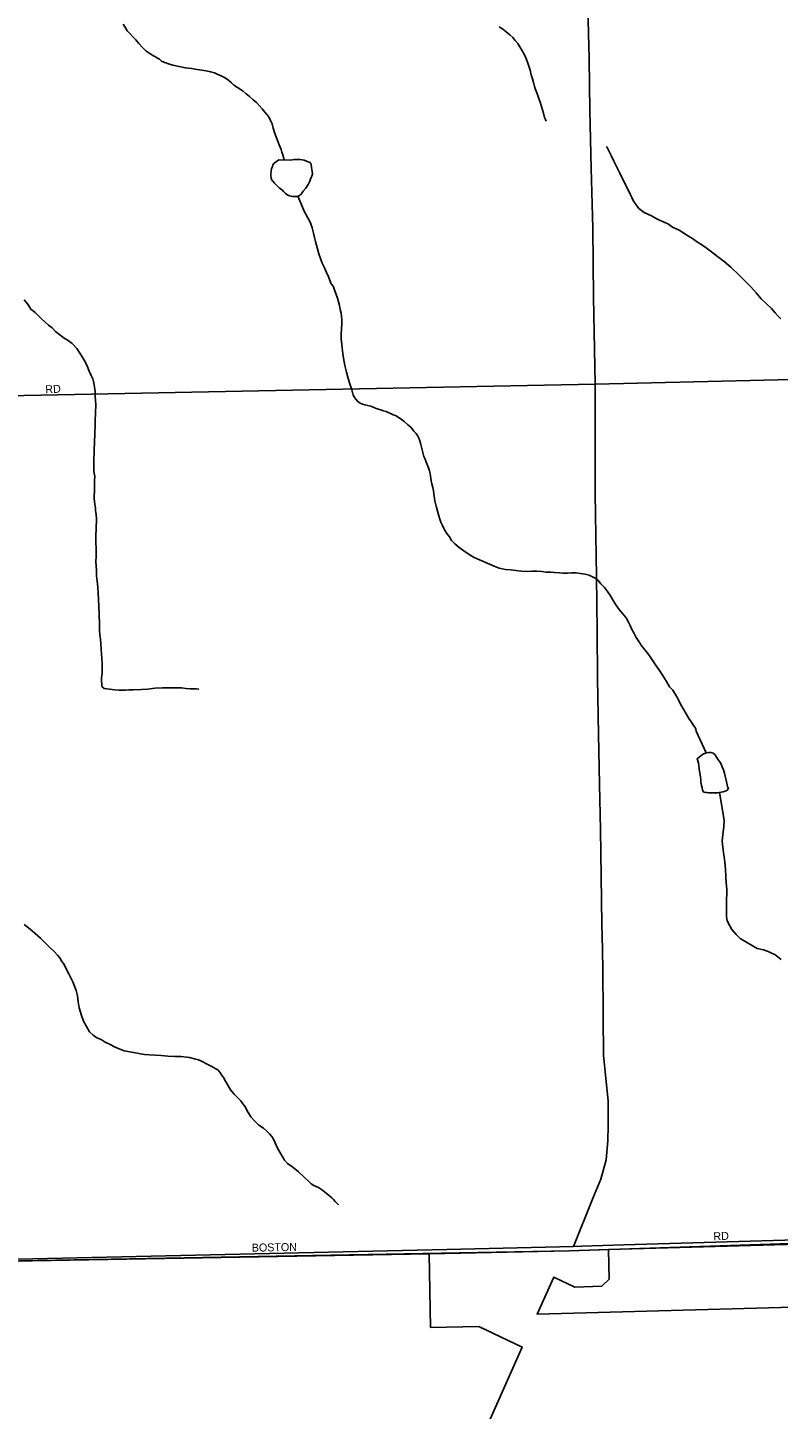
# Model space of a CAD drawing. Extents: x 2010165 to 2382125, y 1060529 to 1407316.
# Drawn here: x 2147720 to 2152412, y 1192922 to 1201555 of the extents above; entities that cross this region are included whole.
import ezdxf

# ---------------------------------------------------------------- set-up
doc = ezdxf.new("R2010")
doc.units = 0
for name, color, linetype in [('GM_X_Adjacent_County', 7, 'Continuous'), ('GM_X_City_Street', 7, 'Continuous'), ('GM_X_City_Street_Text', 7, 'Continuous'), ('GM_X_Corporation', 7, 'Continuous'), ('GM_X_County', 7, 'Continuous'), ('GM_X_Minor_Lake', 7, 'Continuous'), ('GM_X_Minor_River', 7, 'Continuous'), ('GM_X_US_Route', 7, 'Continuous')]:
    doc.layers.add(name, color=color, linetype=linetype)

msp = doc.modelspace()

# ---------------------------------------------------------------- linework, layer by layer
at = {"layer": 'GM_X_Adjacent_County'}
msp.add_lwpolyline([(2158006.9, 1194141.9), (2151106.9, 1193912.6), (2145028.4, 1193800.8), (2144321.2, 1193786.8), (2140581.8, 1193696.4), (2139549.1, 1193676.6), (2134076.1, 1193549.4), (2129443.2, 1193492.7), (2126053.1, 1193488.1), (2117908.3, 1193445.4), (2113522.7, 1193410.7)], dxfattribs=at)
at = {"layer": 'GM_X_City_Street'}
for points in [[(2152235.3, 1199350.5), (2157941.4, 1199486.2)], [(2144971.9, 1199201.6), (2150737.4, 1199316.9)], [(2150737.4, 1199316.9), (2151266.3, 1199327.4)], [(2151266.3, 1199327.4), (2152235.3, 1199350.5)], [(2151447.3, 1193948.6), (2154031.7, 1194024.8)], [(2147752.4, 1193862.6), (2150339.1, 1193921.3)], [(2150339.1, 1193921.3), (2151130.9, 1193939.3), (2151183.6, 1193940.8)], [(2151183.6, 1193940.8), (2151447.3, 1193948.6)], [(2147277.4, 1193851.8), (2147752.4, 1193862.6)]]:
    msp.add_lwpolyline(points, dxfattribs=at)
at = {"layer": 'GM_X_Corporation'}
for points in [[(2154020.1, 1193994.5), (2151351.3, 1193919.5), (2151107.4, 1193912.6), (2150229, 1193893.7), (2145028.4, 1193800.8), (2144321.2, 1193786.8), (2140581.8, 1193696.4), (2139549.1, 1193676.6), (2139563.1, 1207294.1), (2139646.1, 1221239.5)], [(2150282.8, 1192124.7), (2150811.6, 1193309.4), (2150541, 1193440), (2150238.9, 1193433.5), (2150229, 1193893.7), (2151107.4, 1193912.6), (2151351.3, 1193919.5), (2151354.5, 1193736.1), (2151308.4, 1193691.6), (2151140.4, 1193685.8), (2151007.8, 1193747.7), (2150904.4, 1193516.7), (2154025.8, 1193601.1)]]:
    msp.add_lwpolyline(points, dxfattribs=at)
at = {"layer": 'GM_X_County'}
msp.add_lwpolyline([(2158006.9, 1194141.9), (2151106.9, 1193912.6), (2145028.4, 1193800.8), (2144321.2, 1193786.8), (2140581.8, 1193696.4), (2139549.1, 1193676.6), (2139521.7, 1198873.5), (2139522.3, 1201475.3), (2139563.1, 1207294.1), (2139553.6, 1210761.2), (2139571.8, 1213893.1), (2139604.7, 1218402.7), (2139646.1, 1221239.5)], dxfattribs=at)
at = {"layer": 'GM_X_Minor_Lake'}
for points in [[(2149289.2, 1200729.1), (2149275.3, 1200718.8), (2149261.4, 1200708.6), (2149253.5, 1200698.5), (2149249.7, 1200684.4), (2149243.8, 1200674.3), (2149242, 1200658.3), (2149240.2, 1200642.2), (2149240.4, 1200628.1), (2149242.6, 1200616.1), (2149244.7, 1200606.1), (2149252.8, 1200596.2), (2149263, 1200582.3), (2149277.2, 1200568.4), (2149293.5, 1200552.6), (2149311.7, 1200540.7), (2149319.8, 1200530.8), (2149332, 1200518.9), (2149346.1, 1200509.1), (2149356.2, 1200503.2), (2149366.3, 1200501.3), (2149376.3, 1200499.4), (2149392.3, 1200499.6), (2149406.4, 1200499.8), (2149418.3, 1200505.9), (2149430.2, 1200514.1), (2149442, 1200532.3), (2149459.8, 1200552.6), (2149473.5, 1200574.8), (2149483.2, 1200595), (2149491, 1200615.2), (2149496.8, 1200627.3), (2149500.7, 1200639.4), (2149498.5, 1200657.4), (2149496.3, 1200667.4), (2149494.1, 1200683.4), (2149491.9, 1200699.4), (2149485.7, 1200711.4), (2149474.1, 1200717.1)], [(2149474.1, 1200717.1), (2149447.5, 1200727), (2149435.4, 1200728.8), (2149423.4, 1200730.7), (2149407.3, 1200730.5), (2149397.3, 1200730.4), (2149385.3, 1200730.2), (2149375.3, 1200728.1), (2149361.3, 1200727.9), (2149289.2, 1200729.1)], [(2151917.7, 1196923.9), (2151917.4, 1196927), (2151915.1, 1196945), (2151912.9, 1196959.1), (2151908.8, 1196973), (2151904.6, 1196987), (2151937.7, 1197013.2), (2151904.6, 1196987)], [(2151937.7, 1197013.2), (2151950.2, 1197019.7), (2151962.2, 1197023.9), (2151976.2, 1197026), (2151990.2, 1197026.2), (2152004.3, 1197022.4), (2152016.5, 1197010.5), (2152024.6, 1196996.5), (2152036.9, 1196980.6), (2152047.1, 1196966.7), (2152055.3, 1196952.8), (2152061.5, 1196936.8), (2152069.8, 1196916.8), (2152076, 1196896.8), (2152080.3, 1196878.8), (2152084.5, 1196860.8), (2152088.8, 1196842.8), (2152093, 1196824.8), (2152095.2, 1196810.8), (2152101.3, 1196800.8), (2152089.5, 1196788.7), (2152079.5, 1196784.5), (2152067.5, 1196780.4), (2152055.6, 1196778.2), (2152043.6, 1196776.1), (2152031.6, 1196773.9), (2152021.6, 1196773.8), (2152001.5, 1196773.5), (2151991.5, 1196773.4), (2151977.5, 1196773.2), (2151967.4, 1196775.1), (2151957.4, 1196775), (2151945.4, 1196778.9), (2151937.2, 1196790.8), (2151935, 1196806.8), (2151930.8, 1196818.8), (2151928.5, 1196838.9), (2151928.3, 1196854.9), (2151926.1, 1196870.9), (2151917.7, 1196923.9)]]:
    msp.add_lwpolyline(points, dxfattribs=at)
at = {"layer": 'GM_X_Minor_River'}
for points in [[(2148316.4, 1201575.9), (2148330.7, 1201554), (2148341, 1201536), (2148395.8, 1201478.5), (2148414.1, 1201456.7), (2148436.5, 1201432.9), (2148458.8, 1201409.1), (2148483.1, 1201393.3), (2148503.3, 1201381.5), (2148519.4, 1201371.7), (2148531.6, 1201363.8), (2148543.6, 1201357.9), (2148555.8, 1201346.1), (2148572, 1201338.2), (2148606.2, 1201326.6), (2148628.3, 1201320.9), (2148656.4, 1201315.2), (2148706.6, 1201303.8), (2148744.7, 1201300.2), (2148766.9, 1201294.5), (2148795, 1201290.8), (2148835.1, 1201285.3), (2148863.2, 1201279.6), (2148887.4, 1201271.9), (2148905.5, 1201264.1), (2148919.6, 1201258.2), (2148933.7, 1201252.4), (2148945.8, 1201246.5), (2148955.9, 1201238.6), (2148968, 1201232.7), (2148980.2, 1201222.9), (2148994.3, 1201211), (2149008.6, 1201195.1), (2149030.8, 1201181.3), (2149049, 1201169.5), (2149067.2, 1201157.7), (2149085.4, 1201141.9), (2149107.7, 1201124.1), (2149130, 1201104.3), (2149150.2, 1201086.5), (2149168.5, 1201066.7), (2149186.8, 1201046.8), (2149203.1, 1201027), (2149217.3, 1201011.1), (2149229.6, 1200993.2), (2149235.8, 1200979.2), (2149242, 1200967.2), (2149248.2, 1200953.3), (2149254.5, 1200927.3), (2149262.9, 1200899.3), (2149291.9, 1200823.4), (2149298.1, 1200807.4), (2149304.3, 1200793.4), (2149308.6, 1200777.4), (2149312.7, 1200765.5), (2149324.1, 1200728.5)], [(2150666.7, 1201560.6), (2150690.9, 1201544.8), (2150711.1, 1201529), (2150733.5, 1201509.2), (2150751.7, 1201493.4), (2150768, 1201475.5), (2150784.2, 1201455.6), (2150823.2, 1201389.9), (2150833.5, 1201366), (2150843.8, 1201340), (2150852.2, 1201314), (2150860.5, 1201290.1), (2150866.9, 1201260), (2150875.3, 1201236.1), (2150881.6, 1201212.1), (2150887.9, 1201188.1), (2150894.2, 1201168.1), (2150902.5, 1201148.1), (2150908.7, 1201130.1), (2150915, 1201112.1), (2150923.3, 1201090.2), (2150929.5, 1201068.2), (2150937.9, 1201042.2), (2150944.2, 1201020.2), (2150950.6, 1200994.2), (2150956.7, 1200980.2), (2150960.9, 1200970.3)], [(2151339.6, 1200810.4), (2151366.4, 1200756.5), (2151339.6, 1200810.4), (2151366.4, 1200756.5), (2151382.9, 1200720.6), (2151403.4, 1200682.8), (2151421.9, 1200644.9), (2151465.2, 1200557.1), (2151477.5, 1200533.2), (2151487.8, 1200511.2), (2151496, 1200493.3), (2151504.3, 1200475.3), (2151516.6, 1200455.4), (2151528.8, 1200439.5), (2151541, 1200425.6), (2151557.2, 1200411.8), (2151573.4, 1200399.9), (2151595.6, 1200390.2), (2151619.8, 1200378.4), (2151644, 1200364.7), (2151670.2, 1200353), (2151698.4, 1200339.3), (2151724.6, 1200327.6), (2151750.9, 1200307.8), (2151791.2, 1200290.2), (2151821.5, 1200270.6), (2151849.8, 1200252.8), (2151876, 1200237.1), (2151900.3, 1200219.4), (2151928.6, 1200201.6), (2151960.9, 1200180), (2151993.3, 1200154.3), (2152031.8, 1200124.7), (2152074.3, 1200093.1), (2152114.8, 1200057.5), (2152167.5, 1200007.9), (2152204.1, 1199970.3), (2152240.6, 1199934.6), (2152273.2, 1199898.9), (2152305.7, 1199861.2), (2152340.2, 1199827.5), (2152368.6, 1199799.7), (2152393, 1199774), (2152411.3, 1199752.1), (2152427.6, 1199736.3)], [(2149409.2, 1200501.2), (2149449.7, 1200404), (2149484.5, 1200344.2), (2149490.7, 1200328.2), (2149499.1, 1200304.3), (2149507.5, 1200270.3), (2149511.9, 1200244.2), (2149518.2, 1200218.2), (2149524.5, 1200196.2), (2149530.9, 1200172.2), (2149539.3, 1200142.2), (2149549.7, 1200112.3), (2149560.1, 1200084.3), (2149574.5, 1200054.4), (2149588.9, 1200024.5), (2149603.3, 1199994.6), (2149615.8, 1199958.6), (2149632.1, 1199934.7), (2149640.5, 1199910.7), (2149648.8, 1199886.8), (2149657.1, 1199864.8), (2149663.4, 1199840.8), (2149669.7, 1199818.8), (2149674, 1199794.8), (2149680.4, 1199770.8), (2149682.6, 1199750.8), (2149682.9, 1199728.7), (2149683.2, 1199704.6), (2149681.6, 1199672.5), (2149680, 1199642.4), (2149680.5, 1199610.3), (2149682.9, 1199574.2), (2149687.5, 1199534.1), (2149694.1, 1199490.1), (2149702.7, 1199444), (2149713.2, 1199402), (2149723.8, 1199362), (2149736.3, 1199324), (2149746.7, 1199292.1), (2149755.2, 1199258.1), (2149769.5, 1199236.2), (2149783.8, 1199218.3), (2149797.9, 1199208.4), (2149812, 1199202.6), (2149828.1, 1199198.8), (2149846.2, 1199195), (2149864.3, 1199189.2), (2149884.4, 1199181.4), (2149904.5, 1199173.6), (2149926.7, 1199165.9), (2149942.8, 1199160), (2149960.9, 1199156.2), (2149993.1, 1199142.6), (2150005.2, 1199136.7), (2150019.3, 1199130.9), (2150035.5, 1199121), (2150055.7, 1199107.2), (2150073.9, 1199093.4), (2150094.2, 1199075.6), (2150114.4, 1199057.8), (2150132.8, 1199034), (2150149, 1199018.1), (2150157.2, 1199006.2), (2150165.4, 1198990.2), (2150171.6, 1198972.2), (2150177.9, 1198950.2), (2150184.3, 1198926.2), (2150190.6, 1198900.2), (2150196.9, 1198876.2), (2150205.2, 1198858.3), (2150211.4, 1198840.3), (2150217.6, 1198826.3), (2150225.9, 1198804.4), (2150232.2, 1198786.4), (2150236.4, 1198768.4), (2150238.6, 1198752.3), (2150240.8, 1198738.3), (2150243, 1198724.3), (2150247.3, 1198704.3), (2150251.6, 1198682.3), (2150255.9, 1198660.3), (2150258.1, 1198642.2), (2150260.3, 1198628.2), (2150262.5, 1198612.2), (2150264.7, 1198598.2), (2150268.9, 1198582.2), (2150273.2, 1198564.2), (2150279.5, 1198542.2), (2150285.8, 1198518.2), (2150294.2, 1198490.2), (2150302.5, 1198464.2), (2150312.8, 1198444.3), (2150321, 1198426.3), (2150329.3, 1198410.3), (2150339.5, 1198394.4), (2150355.8, 1198372.6), (2150370.1, 1198350.7), (2150390.4, 1198328.8)], [(2147697.8, 1199854.8), (2147720.2, 1199827), (2147740.7, 1199795.1), (2147767, 1199775.4), (2147785.3, 1199755.6), (2147805.6, 1199735.8), (2147827.9, 1199716), (2147850.2, 1199696.2), (2147872.4, 1199678.4), (2147894.8, 1199656.6), (2147921.1, 1199634.8), (2147947.4, 1199615.1), (2147973.7, 1199599.4), (2147997.9, 1199581.6), (2148026.4, 1199549.9), (2148046.8, 1199522), (2148065.2, 1199492.1), (2148081.6, 1199462.2), (2148094, 1199436.3), (2148104.4, 1199408.3), (2148116.7, 1199382.4), (2148127, 1199360.5), (2148133.4, 1199336.5), (2148137.7, 1199308.4), (2148142.1, 1199282.4), (2148142.5, 1199250.3), (2148144.8, 1199228.3), (2148145.2, 1199198.2), (2148142.5, 1199097.8), (2148141, 1199061.7), (2148139.4, 1199031.6), (2148139.8, 1199001.5), (2148138, 1198979.4), (2148138.4, 1198955.3), (2148136.8, 1198925.2), (2148135.2, 1198889.1), (2148133.5, 1198865), (2148133.8, 1198840.9), (2148134.2, 1198812.8), (2148134.5, 1198790.7), (2148136.8, 1198770.7), (2148139, 1198750.7), (2148137.3, 1198726.6), (2148137.6, 1198704.5), (2148137.9, 1198682.4), (2148138.3, 1198656.4), (2148136.6, 1198630.2), (2148136.8, 1198612.2), (2148137.1, 1198594.1), (2148139.3, 1198578.1), (2148141.5, 1198564.1), (2148143.7, 1198550.1), (2148143.8, 1198538.1), (2148146, 1198526), (2148148.1, 1198514), (2148150.5, 1198483.9), (2148146, 1198373.5), (2148146.5, 1198335.4), (2148148.9, 1198303.3), (2148149.2, 1198277.3), (2148147.6, 1198249.2), (2148146, 1198219.1), (2148148.3, 1198193), (2148150.8, 1198160.9), (2148151.2, 1198128.8), (2148153.6, 1198096.7), (2148158.1, 1198058.7), (2148160.6, 1198020.6), (2148165.7, 1197940.4), (2148169.1, 1197830.1), (2148169.6, 1197791.9), (2148172, 1197759.9), (2148174.4, 1197733.8), (2148176.8, 1197705.8), (2148179.2, 1197671.7), (2148181.6, 1197641.6)], [(2150390.4, 1198328.8), (2150416.8, 1198307.1), (2150447.1, 1198285.4), (2150479.4, 1198263.7), (2150511.7, 1198244.1), (2150606.4, 1198203.1), (2150636.7, 1198189.4), (2150666.9, 1198177.7), (2150707, 1198170.2), (2150737.1, 1198166.6), (2150771.2, 1198163), (2150807.4, 1198159.4), (2150841.4, 1198157.8), (2150871.5, 1198158.2), (2150903.5, 1198158.6), (2150933.6, 1198156.9), (2150961.7, 1198153.3), (2150989.8, 1198151.6), (2151013.8, 1198149.9), (2151043.9, 1198148.2), (2151068, 1198146.5), (2151094, 1198146.9), (2151120, 1198149.2), (2151148.1, 1198147.5), (2151176.2, 1198143.8), (2151204.3, 1198140.2), (2151230.4, 1198134.5), (2151250.6, 1198122.7), (2151270.8, 1198112.9), (2151284.9, 1198101), (2151303.3, 1198079.2), (2151325.6, 1198057.4), (2151344, 1198031.6), (2151362.3, 1198003.7), (2151378.7, 1197975.8), (2151397.1, 1197947.9), (2151417.5, 1197920.1), (2151439.9, 1197892.3), (2151460.3, 1197866.4), (2151474.7, 1197840.5), (2151485, 1197818.6), (2151495.3, 1197798.6), (2151509.6, 1197772.7), (2151524, 1197744.8), (2151540.4, 1197718.9), (2151558.8, 1197691.1), (2151579.1, 1197665.2), (2151601.6, 1197635.4), (2151624, 1197605.6), (2151644.5, 1197573.7), (2151669, 1197537.9), (2151691.5, 1197502.1), (2151713.9, 1197470.3), (2151732.4, 1197436.4), (2151752.7, 1197414.6), (2151783.4, 1197362.8), (2151793.7, 1197340.8), (2151806.1, 1197316.9), (2151820.4, 1197293), (2151836.8, 1197267.1), (2151853.2, 1197239.2), (2151869.5, 1197215.3), (2151881.8, 1197195.4), (2151892, 1197181.5), (2151896.1, 1197171.5), (2151898.3, 1197159.5), (2151961.5, 1197023.6)], [(2148181.6, 1197641.6), (2148184, 1197613.6), (2148186.4, 1197583.5), (2148186.7, 1197559.4), (2148184.9, 1197541.3), (2148185.2, 1197523.3), (2148183.4, 1197505.2), (2148181.5, 1197493.1), (2148181.7, 1197481.1), (2148181.9, 1197469.1), (2148184.1, 1197455.1), (2148184.3, 1197439), (2148198.5, 1197425.1), (2148230.6, 1197421.5), (2148264.7, 1197417.9), (2148290.7, 1197416.2), (2148310.8, 1197414.5), (2148330.8, 1197414.7), (2148352.8, 1197417), (2148380.9, 1197417.3), (2148430.9, 1197420), (2148471, 1197422.4), (2148515, 1197427), (2148563, 1197429.6), (2148609.1, 1197430.2), (2148647.2, 1197430.6), (2148681.3, 1197429.1), (2148709.3, 1197425.4), (2148735.4, 1197423.7), (2148757.4, 1197424), (2148773.5, 1197424.2), (2148787.5, 1197422.3), (2148789.5, 1197422.3)], [(2152043.5, 1196776), (2152073.9, 1196603.9), (2152072.4, 1196563.7), (2152065.1, 1196511.5), (2152061.5, 1196473.3), (2152066.1, 1196433.2), (2152070.7, 1196387.1), (2152077.3, 1196343.1), (2152081.9, 1196297), (2152084.5, 1196250.9), (2152087, 1196210.8), (2152089.5, 1196172.7), (2152089.9, 1196140.6), (2152088.3, 1196110.5), (2152088.8, 1196076.3), (2152089.1, 1196050.3), (2152087.4, 1196032.2), (2152087.6, 1196014.1), (2152087.7, 1196002.1), (2152090, 1195986.1), (2152092.1, 1195976.1), (2152098.3, 1195962.1), (2152108.6, 1195942.2), (2152120.9, 1195920.2), (2152149.3, 1195888.5), (2152173.7, 1195862.7), (2152280.7, 1195801.8), (2152318.9, 1195792.3), (2152349.1, 1195782.6), (2152369.2, 1195772.8), (2152385.4, 1195765), (2152399.5, 1195757.1), (2152411.6, 1195747.2), (2152429.8, 1195733.4)], [(2147698.9, 1195950.3), (2147735.3, 1195922.6), (2147767.7, 1195894.9), (2147800.2, 1195865.2), (2147830.6, 1195833.5), (2147861.1, 1195805.8), (2147885.4, 1195782), (2147905.7, 1195760.2), (2147922, 1195742.3), (2147934.3, 1195720.4), (2147944.5, 1195706.5), (2147954.7, 1195688.5), (2147965.1, 1195666.6), (2147977.4, 1195642.7), (2147989.7, 1195618.7), (2148002.1, 1195592.8), (2148012.4, 1195566.8), (2148022.8, 1195538.9), (2148031.3, 1195504.9), (2148035.8, 1195468.8), (2148042.3, 1195430.8), (2148056.9, 1195382.8), (2148069.4, 1195346.8), (2148087.9, 1195313), (2148106.3, 1195281.1), (2148128.7, 1195259.3), (2148152.9, 1195243.5), (2148179.1, 1195231.8), (2148205.4, 1195216.1), (2148235.6, 1195200.4), (2148263.8, 1195186.7), (2148292, 1195175), (2148322.3, 1195161.3), (2148404.6, 1195146.3), (2148424.7, 1195142.5), (2148450.8, 1195138.8), (2148480.9, 1195137.2), (2148516.9, 1195135.6), (2148555.1, 1195132.1)], [(2148555.1, 1195132.1), (2148595.2, 1195128.6), (2148637.3, 1195127.1), (2148679.3, 1195125.6), (2148731.5, 1195120.2), (2148763.7, 1195112.6), (2148787.8, 1195104.8), (2148805.9, 1195097.1), (2148820, 1195091.2), (2148834.2, 1195083.3), (2148850.3, 1195073.5), (2148870.5, 1195063.7), (2148892.7, 1195052), (2148908.8, 1195042.1), (2148921, 1195028.2), (2148931.3, 1195012.3), (2148943.5, 1194994.4), (2148955.8, 1194972.5), (2148970.2, 1194946.6), (2148988.6, 1194918.7), (2149011, 1194890.9), (2149033.3, 1194869.1), (2149051.6, 1194849.2), (2149065.9, 1194831.4), (2149076.1, 1194817.4), (2149084.2, 1194805.5), (2149094.5, 1194783.6), (2149102.7, 1194769.6), (2149115, 1194749.7), (2149137.4, 1194723.9), (2149165.8, 1194698.2), (2149194.1, 1194678.4), (2149216.4, 1194658.6), (2149232.6, 1194642.8), (2149246.8, 1194626.9), (2149257.1, 1194609), (2149267.4, 1194587), (2149279.8, 1194557.1), (2149296.2, 1194529.2), (2149310.6, 1194503.3), (2149324.9, 1194479.4), (2149345.2, 1194457.6), (2149377.6, 1194433.9), (2149412, 1194406.2), (2149478.9, 1194342.8), (2149493.1, 1194331), (2149509.3, 1194321.1), (2149537.5, 1194307.4), (2149557.7, 1194295.6), (2149573.9, 1194281.8), (2149588.1, 1194269.9), (2149606.3, 1194256.1), (2149620.5, 1194244.2), (2149632.7, 1194232.4), (2149642.8, 1194220.4), (2149659.1, 1194204.6), (2149661.1, 1194202.6), (2149661.1, 1194204.6)]]:
    msp.add_lwpolyline(points, dxfattribs=at)
at = {"layer": 'GM_X_US_Route'}
for points in [[(2151268, 1198642.3), (2151267, 1198705.7), (2151266.3, 1199327.4), (2151255.9, 1199870.9), (2151252, 1200302.1), (2151242.4, 1200677.1), (2151234.8, 1201038.1), (2151229.4, 1201360.9), (2151222, 1201679.8), (2151221, 1201896.3), (2151219.9, 1202145), (2151222.8, 1202399.8), (2151221.9, 1202610.3), (2151216.5, 1202927.2), (2151209.3, 1203197.9), (2151200.1, 1203484.6), (2151198.7, 1203789.5), (2151199.5, 1204064.2), (2151197.3, 1204185.3)], [(2151312.1, 1195796.5), (2151309.1, 1195954.1), (2151305.7, 1196251), (2151300.5, 1196543.8), (2151295.2, 1196826.5), (2151287.9, 1197139.4), (2151282.3, 1197488.4), (2151279, 1197783.2), (2151275.6, 1198126.1), (2151268, 1198642.3)], [(2151130.9, 1193939.3), (2151250.6, 1194234.9), (2151301.9, 1194359.8), (2151335.4, 1194480.4), (2151346.5, 1194598.6), (2151348.7, 1194694.6), (2151348.7, 1194848.5), (2151318.6, 1195131.9), (2151317.5, 1195380.6), (2151314.2, 1195685.4), (2151312.5, 1195776.8), (2151312.1, 1195796.5)]]:
    msp.add_lwpolyline(points, dxfattribs=at)

# ---------------------------------------------------------------- texts
at = {"layer": 'GM_X_City_Street_Text'}
for s, rotation, p in [('RD', 3.01098, (2147831.8, 1199269.6)), ('RD', 3.01098, (2152007.4, 1193977)), ('BOSTON', 1.02247, (2149121.3, 1193906.7))]:
    msp.add_text(s, height=50, rotation=rotation, dxfattribs=at).set_placement(p)

doc.saveas('drawing.dxf')
